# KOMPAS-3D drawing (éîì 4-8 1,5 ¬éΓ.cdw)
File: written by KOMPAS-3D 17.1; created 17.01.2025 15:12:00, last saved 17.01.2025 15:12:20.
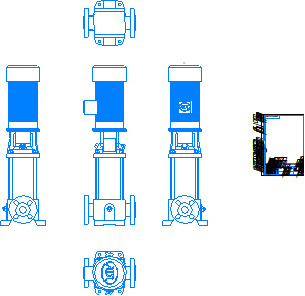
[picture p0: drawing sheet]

Sheet 1: A4, portrait

Title block, sheet 1: name: ВМН 4-8 1,5 кВт; designation: ВМН 4-8 1,5 кВт; sheets: 1; sheet format: A4; stored path: \\adlc.lan\data\АДЛ_ПКД\3D-модели\ADL production\Насосы ГРАНПАМП\Насосы ВМН\ВМН4\KOMPAS 2D\ВМН 4-8 1,5 кВт.cdw

Views: Проекционный вид 2, Проекционный вид 3, Проекционный вид 4, Проекционный вид 5
Referenced files in \\adlc.lan\data\АДЛ_ПКД\3D-модели\ADL production\Насосы ГРАНПАМП\Насосы ВМН\ВМН4\KOMPAS 3D\: ВМН 4-8 1,5 кВт.m3d
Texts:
  Andrey
  АДЛ
Dimensions and other numbers on the sheet: 1:1; 1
